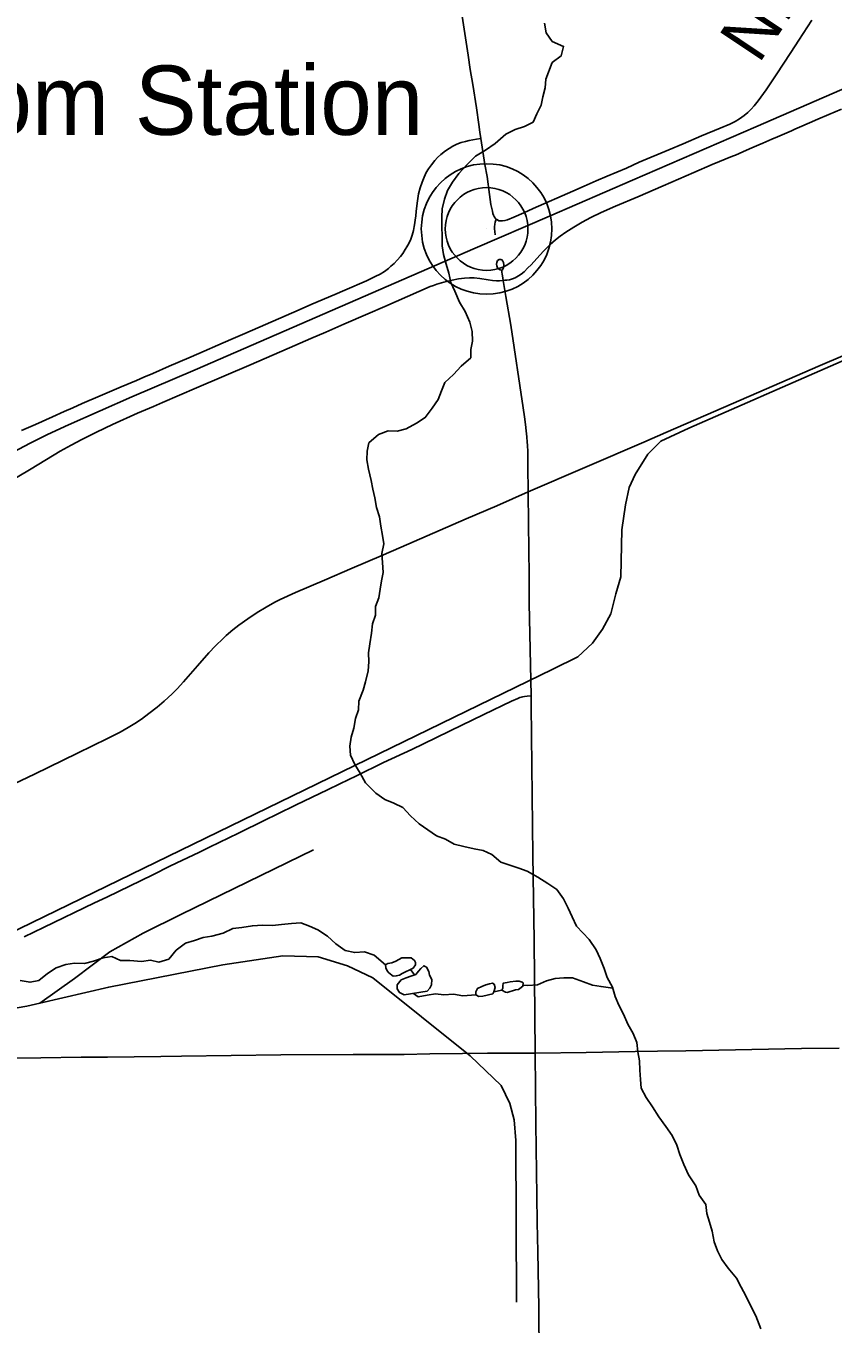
# Model space of a CAD drawing. Extents: x 0 to 34, y 0 to 22.
# Drawn here: x 14.293 to 16.593, y 8.341 to 12.039 of the extents above; entities that cross this region are included whole.
import ezdxf

# ---------------------------------------------------------------- set-up
doc = ezdxf.new("R2010")
doc.units = 0
for name, color, linetype in [('GM_X_County_Road', 7, 'Continuous'), ('GM_X_County_Road_Text', 7, 'Continuous'), ('GM_X_Minor_Lake', 7, 'Continuous'), ('GM_X_Minor_River', 7, 'Continuous'), ('GM_X_Rail_Line', 7, 'Continuous'), ('GM_X_Township_Road', 7, 'Continuous'), ('GM_X_Unincorporated', 7, 'Continuous'), ('GM_X_Unincorporated_Location', 7, 'Continuous'), ('GM_X_Unincorporated_Text', 7, 'Continuous')]:
    doc.layers.add(name, color=color, linetype=linetype)

msp = doc.modelspace()

# ---------------------------------------------------------------- linework, layer by layer
at = {"layer": 'GM_X_County_Road'}
for points in [[(15.5893, 11.7179), (15.5867, 11.7367), (15.5837, 11.7582), (15.5764, 11.8058), (15.5661, 11.8717), (15.5592, 11.9146), (15.5526, 11.956), (15.5417, 12.0297), (15.5308, 12.0972)], [(15.6332, 11.4882), (15.6368, 11.4861), (15.6409, 11.4841), (15.6458, 11.4832), (15.6512, 11.4833), (15.6578, 11.4843), (15.6648, 11.4865), (15.6833, 11.4942), (15.7118, 11.5064), (15.7387, 11.5184), (15.8512, 11.5678), (15.8839, 11.5822), (15.918, 11.5973), (15.9493, 11.6112), (16.0038, 11.6338), (16.0406, 11.6504), (16.1251, 11.6862), (16.1653, 11.7028), (16.2181, 11.7256), (16.2712, 11.7476), (16.2982, 11.7593), (16.3134, 11.7669), (16.3266, 11.7747), (16.3392, 11.7835), (16.3497, 11.7923), (16.3596, 11.802), (16.3678, 11.8112), (16.3791, 11.8258), (16.4017, 11.8573), (16.4304, 11.8998), (16.4725, 11.9632), (16.4953, 11.9985), (16.5327, 12.0557)], [(15.6332, 11.4882), (15.6301, 11.4912), (15.627, 11.4956), (15.6252, 11.4995), (15.6236, 11.5046), (15.6222, 11.5108), (15.6181, 11.5305), (15.6142, 11.5585), (15.6068, 11.6102), (15.6007, 11.6446), (15.5893, 11.7179)], [(15.6303, 11.4436), (15.6288, 11.4534), (15.6283, 11.4611), (15.6285, 11.4665), (15.629, 11.4742), (15.6301, 11.4794), (15.6332, 11.4882)]]:
    msp.add_lwpolyline(points, dxfattribs=at)
at = {"layer": 'GM_X_Minor_Lake'}
for p, q in [((15.3651, 9.339), (15.3961, 9.3546)), ((15.3705, 9.2783), (15.4367, 9.2886)), ((15.6639, 9.2855), (15.6875, 9.2924)), ((15.5949, 9.2752), (15.6233, 9.2813))]:
    msp.add_line(p, q, dxfattribs=at)
for points in [[(15.3961, 9.3546), (15.4027, 9.3641), (15.4026, 9.3708), (15.4006, 9.3764), (15.3911, 9.3839), (15.3788, 9.3838), (15.3636, 9.3836), (15.3467, 9.3749), (15.3354, 9.37), (15.324, 9.3679), (15.3174, 9.3641), (15.3185, 9.3555), (15.3224, 9.347), (15.3272, 9.3414), (15.3396, 9.3321), (15.3481, 9.3322), (15.3576, 9.3342), (15.3651, 9.339)], [(15.4367, 9.2886), (15.4441, 9.2972), (15.4488, 9.3068), (15.4495, 9.322), (15.4428, 9.3342), (15.4408, 9.3446), (15.434, 9.3569), (15.4264, 9.3615), (15.4179, 9.3539), (15.4114, 9.3462), (15.4039, 9.3366), (15.3898, 9.3317), (15.3766, 9.3268), (15.3624, 9.3209), (15.3503, 9.3066), (15.3504, 9.2961), (15.3572, 9.2848), (15.3705, 9.2783)], [(15.6233, 9.2813), (15.626, 9.287), (15.6297, 9.2994), (15.6267, 9.3088), (15.622, 9.3116), (15.6135, 9.3096), (15.6031, 9.3067), (15.5918, 9.3027), (15.5795, 9.2969), (15.5749, 9.2873), (15.575, 9.2788), (15.5836, 9.2742), (15.5949, 9.2752)], [(15.6875, 9.2924), (15.696, 9.2935), (15.6998, 9.2964), (15.7092, 9.3031), (15.71, 9.3126), (15.7072, 9.3145), (15.6986, 9.3173), (15.6939, 9.3172), (15.6891, 9.3171), (15.6731, 9.316), (15.6646, 9.314), (15.6532, 9.312), (15.6514, 9.3044), (15.6515, 9.2977), (15.6487, 9.292), (15.6592, 9.2864), (15.6639, 9.2855)]]:
    msp.add_lwpolyline(points, dxfattribs=at)
at = {"layer": 'GM_X_Minor_River'}
for points in [[(15.6302, 11.7038), (15.6602, 11.7307), (15.6866, 11.7434), (15.7139, 11.7522), (15.7384, 11.7648), (15.7486, 11.7887), (15.7615, 11.8135), (15.766, 11.8373), (15.7724, 11.8621), (15.774, 11.8868), (15.7924, 11.9345), (15.8177, 11.9537), (15.825, 11.9804), (15.7927, 11.9943), (15.7753, 12.0197), (15.7703, 12.0472)], [(15.9289, 9.3816), (15.9182, 9.4071), (15.898, 9.4363), (15.8616, 9.4739), (15.849, 9.5003), (15.8383, 9.5258), (15.8247, 9.5522), (15.8055, 9.5786), (15.7797, 9.5953), (15.7511, 9.614), (15.7216, 9.6307), (15.6978, 9.639), (15.6721, 9.6482), (15.6465, 9.6564), (15.6207, 9.678), (15.5959, 9.69), (15.5703, 9.6945), (15.5409, 9.7008), (15.5133, 9.708), (15.4886, 9.722), (15.4629, 9.7312), (15.4381, 9.7489), (15.4133, 9.7657), (15.3884, 9.7882), (15.3673, 9.8127), (15.3416, 9.8247), (15.3159, 9.8348), (15.2902, 9.8535), (15.2605, 9.8826), (15.245, 9.9099), (15.2305, 9.9345), (15.2179, 9.9609), (15.2157, 9.9874), (15.2193, 10.0122), (15.2275, 10.0379), (15.2319, 10.0655), (15.2402, 10.0902), (15.2418, 10.1149), (15.2537, 10.1464), (15.2601, 10.1702), (15.2683, 10.2016), (15.2699, 10.2273), (15.2686, 10.2529), (15.2731, 10.2786), (15.2775, 10.309), (15.28, 10.3356), (15.2892, 10.3604), (15.2889, 10.3851), (15.2981, 10.4098), (15.3026, 10.4346), (15.3061, 10.4583), (15.3106, 10.4821), (15.3093, 10.5106), (15.3071, 10.5362), (15.3125, 10.5638), (15.3094, 10.5875), (15.3043, 10.614), (15.3003, 10.6405), (15.2914, 10.667), (15.2873, 10.6945), (15.2814, 10.7191), (15.2764, 10.7437), (15.2694, 10.7759), (15.2644, 10.8024), (15.265, 10.8271), (15.2704, 10.8509), (15.2976, 10.875), (15.325, 10.8857), (15.3506, 10.8841), (15.376, 10.8911), (15.4062, 10.9076), (15.4306, 10.923), (15.4502, 10.9498), (15.4679, 10.9747), (15.4771, 10.9995), (15.4863, 11.0234), (15.5116, 11.0455), (15.5331, 11.0695), (15.5603, 11.0935), (15.561, 11.1173), (15.5655, 11.141), (15.5642, 11.1685), (15.5582, 11.1951), (15.5446, 11.2253), (15.5282, 11.2517), (15.5146, 11.2828), (15.5039, 11.3083), (15.498, 11.3349), (15.4901, 11.3604), (15.4832, 11.3878), (15.4791, 11.4125), (15.4782, 11.4941), (15.4789, 11.5179), (15.4852, 11.5455), (15.4944, 11.5702), (15.5083, 11.5941), (15.526, 11.6181), (15.5504, 11.644), (15.5738, 11.668), (15.602, 11.6854), (15.6302, 11.7038)], [(15.3174, 9.3641), (15.285, 9.3912), (15.2574, 9.4013), (15.2299, 9.3991), (15.2024, 9.4045), (15.1757, 9.4241), (15.1518, 9.4457), (15.1251, 9.4634), (15.1013, 9.4745), (15.0766, 9.4837), (15.0501, 9.4815), (15.0207, 9.4793), (14.9952, 9.4761), (14.9668, 9.4767), (14.9384, 9.4755), (14.9082, 9.4704), (14.8826, 9.4672), (14.8553, 9.4546), (14.8223, 9.4456), (14.7977, 9.4416), (14.7732, 9.4337), (14.7477, 9.4258), (14.7214, 9.4055), (14.6999, 9.3806), (14.6716, 9.3718), (14.6479, 9.3772), (14.6224, 9.3731), (14.5892, 9.3765), (14.5627, 9.3762), (14.538, 9.3873), (14.5134, 9.3841), (14.4851, 9.3743), (14.4596, 9.3674), (14.4312, 9.3689), (14.4066, 9.3649), (14.3792, 9.3551), (14.3548, 9.3396), (14.3295, 9.3194), (14.3049, 9.3143), (14.2764, 9.3197)], [(16.3868, 8.3268), (16.3731, 8.3637), (16.3596, 8.3901), (16.3441, 8.4212), (16.3305, 8.4458), (16.3179, 8.4712), (16.2939, 8.4994), (16.2757, 8.5248), (16.2631, 8.5494), (16.2543, 8.5749), (16.2482, 8.6052), (16.2404, 8.6307), (16.2335, 8.6553), (16.2303, 8.6809), (16.2111, 8.7082), (16.2013, 8.7347), (16.1811, 8.7657), (16.1675, 8.795), (16.1558, 8.8233), (16.148, 8.8498), (16.1344, 8.8781), (16.1161, 8.9036), (16.0959, 8.9308), (16.0785, 8.9591), (16.0602, 8.9864), (16.0457, 9.0128), (16.0445, 9.0375), (16.0423, 9.064), (16.0411, 9.0906), (16.0361, 9.1162), (16.0339, 9.1427), (16.0232, 9.1682), (16.0077, 9.1946), (15.996, 9.223), (15.9825, 9.2494), (15.9718, 9.2739), (15.9639, 9.3004), (15.9494, 9.3278), (15.9406, 9.3533), (15.9289, 9.3816)], [(15.4004, 9.3354), (15.3885, 9.3507)], [(15.9648, 9.2974), (15.9317, 9.3019), (15.907, 9.3064), (15.8814, 9.3156), (15.85, 9.3266), (15.8254, 9.3273), (15.8008, 9.3251), (15.7762, 9.3182), (15.7508, 9.3074), (15.7234, 9.3052), (15.7094, 9.306)], [(15.575, 9.2788), (15.5381, 9.2755), (15.5116, 9.28), (15.4841, 9.2787), (15.4604, 9.2813), (15.4358, 9.2772), (15.4103, 9.2731), (15.3975, 9.2825)], [(15.6487, 9.292), (15.6261, 9.2872)]]:
    msp.add_lwpolyline(points, dxfattribs=at)
at = {"layer": 'GM_X_Rail_Line'}
for points in [[(18.6712, 11.9797), (17.7965, 11.5996), (16.1817, 10.893), (16.1016, 10.8556), (16.0651, 10.819), (16.0291, 10.7614), (16.0117, 10.7238), (16.0013, 10.6748), (15.9912, 10.6032), (15.988, 10.4696), (15.9742, 10.4211), (15.9592, 10.364), (15.9356, 10.3204), (15.9074, 10.2808), (15.8654, 10.2415), (15.7943, 10.2063), (14.1322, 9.3985), (13.8231, 9.242), (13.7678, 9.2202), (13.679, 9.1945)], [(14.2563, 10.8249), (14.3049, 10.8506), (14.3545, 10.8748), (14.4143, 10.9027), (14.595, 10.9819), (14.775, 11.0593), (15.0072, 11.1599), (15.5727, 11.4055), (15.7849, 11.4972), (16.0211, 11.5991), (16.3726, 11.7519), (16.8851, 11.9739)], [(14.3323, 9.2546), (14.4312, 9.325), (14.5322, 9.4011), (14.6274, 9.4541), (14.7359, 9.5079), (15.1124, 9.6913)], [(14.3323, 9.2546), (14.5287, 9.3006), (14.8537, 9.3637), (15.0248, 9.39), (15.1252, 9.3865), (15.2093, 9.3613), (15.2816, 9.3272), (15.5584, 9.1048), (15.6474, 9.0205), (15.6721, 8.9691), (15.6841, 8.9223), (15.689, 8.8631), (15.6906, 8.4032)], [(13.679, 9.1945), (13.8272, 9.187), (14.0474, 9.2037), (14.2951, 9.2459), (14.3323, 9.2546)]]:
    msp.add_lwpolyline(points, dxfattribs=at)
at = {"layer": 'GM_X_Township_Road'}
for points in [[(16.1163, 10.8804), (16.2304, 10.9297), (16.4029, 11.0046), (16.5498, 11.0682), (16.7054, 11.1353), (16.8238, 11.1864), (16.9594, 11.2449), (17.0179, 11.2701), (17.1618, 11.3327), (17.2616, 11.376), (17.4399, 11.4533), (17.5883, 11.5174), (17.7723, 11.597), (17.8978, 11.6513), (18.0734, 11.727), (18.3016, 11.8257), (18.4757, 11.9009), (18.5727, 11.9429), (18.6712, 11.9855)], [(14.3906, 10.827), (14.4218, 10.8445), (14.452, 10.8604), (14.4937, 10.8812), (14.54, 10.9033), (14.6108, 10.9353), (14.6564, 10.9551), (14.6822, 10.9659), (14.7792, 11.0077), (14.9347, 11.0747), (15.0588, 11.1283), (15.1045, 11.148), (15.1472, 11.1666), (15.1984, 11.1891), (15.2668, 11.2189), (15.3152, 11.24), (15.445, 11.2961), (15.4538, 11.2996), (15.464, 11.3028), (15.4833, 11.3087), (15.5075, 11.3147), (15.5257, 11.3183), (15.5427, 11.3205), (15.5566, 11.3214), (15.5706, 11.3209), (15.586, 11.3189), (15.6104, 11.3153), (15.6227, 11.3136), (15.6335, 11.3127), (15.6419, 11.3127), (15.6529, 11.3138), (15.6575, 11.3142), (15.6628, 11.3149), (15.6704, 11.316), (15.6794, 11.3186), (15.6865, 11.3216), (15.6961, 11.3266), (15.7039, 11.3318), (15.7123, 11.3386), (15.7235, 11.3494), (15.7321, 11.3584), (15.7572, 11.3859), (15.769, 11.3983), (15.7866, 11.4158), (15.8017, 11.4293), (15.815, 11.4399), (15.8315, 11.4516), (15.8537, 11.4659), (15.8779, 11.48), (15.9026, 11.4931), (15.9321, 11.5071), (15.9733, 11.5254), (16.0361, 11.5523), (16.1089, 11.5838), (16.196, 11.6211), (16.2487, 11.6438), (16.306, 11.6675), (16.3145, 11.6711), (16.3459, 11.6846), (16.3616, 11.6914), (16.3816, 11.6999), (16.393, 11.7048), (16.4186, 11.7159), (16.4343, 11.7227), (16.4613, 11.7345), (16.4741, 11.7402), (16.4841, 11.7445), (16.4969, 11.7501), (16.5253, 11.7625), (16.5496, 11.773), (16.5809, 11.7866), (16.6165, 11.8021)], [(14.28, 10.8865), (14.32, 10.9034), (14.3683, 10.9248), (14.4022, 10.9401), (14.4263, 10.951), (14.4533, 10.9629), (14.5045, 10.9854), (14.5644, 11.0109), (14.6076, 11.0285), (14.6289, 11.0378), (14.6545, 11.0488), (14.7015, 11.0693), (14.757, 11.0937), (14.7855, 11.1059), (14.8554, 11.1362), (14.8839, 11.1485), (14.9167, 11.1627), (15.0349, 11.2143), (15.0719, 11.2303), (15.1075, 11.246), (15.1732, 11.2741), (15.2017, 11.2864), (15.2629, 11.3129), (15.2882, 11.3248), (15.3019, 11.3319), (15.315, 11.3397), (15.3258, 11.3477), (15.3329, 11.3542), (15.3421, 11.3622), (15.3508, 11.3716), (15.3598, 11.382), (15.3668, 11.391), (15.374, 11.4015), (15.3787, 11.4093), (15.3836, 11.4191), (15.3894, 11.4316), (15.3938, 11.443), (15.3974, 11.4563), (15.3994, 11.4672), (15.4011, 11.4782), (15.4022, 11.4867), (15.4038, 11.4974), (15.4052, 11.5112), (15.4089, 11.5406), (15.412, 11.5607), (15.4162, 11.5774), (15.4216, 11.5938), (15.4275, 11.6084), (15.4338, 11.6211), (15.4402, 11.6319), (15.4482, 11.6436), (15.458, 11.6558), (15.4655, 11.6639), (15.4747, 11.6725), (15.4885, 11.683), (15.4989, 11.6901), (15.5098, 11.6964), (15.5211, 11.7019), (15.5329, 11.7065), (15.545, 11.71), (15.5558, 11.7124), (15.5666, 11.7142), (15.5772, 11.7159), (15.5893, 11.7179)], [(15.7202, 10.866), (15.7201, 10.8682), (15.7182, 10.8853), (15.7161, 10.9031), (15.7132, 10.9256), (15.7095, 10.9506), (15.6742, 11.1866), (15.6605, 11.2679), (15.6529, 11.3138), (15.6506, 11.3273), (15.6498, 11.3321), (15.649, 11.3378), (15.6488, 11.3403), (15.6493, 11.343), (15.6506, 11.3445), (15.652, 11.3463), (15.6537, 11.3494), (15.6547, 11.3536), (15.6545, 11.3587), (15.6535, 11.3649), (15.652, 11.3692), (15.649, 11.3726), (15.6462, 11.3737), (15.6418, 11.3737), (15.637, 11.3704), (15.6345, 11.3648), (15.6342, 11.36), (15.635, 11.3554), (15.6369, 11.3495), (15.6407, 11.3461), (15.6446, 11.344), (15.6482, 11.3429)], [(15.7244, 10.7117), (16.0534, 10.8533), (16.1163, 10.8804)], [(15.7581, 8.1139), (15.7548, 8.3455), (15.7544, 8.3875), (15.7518, 8.546), (15.7498, 8.6299), (15.7488, 8.7061), (15.7458, 8.9113), (15.744, 9.1126), (15.7412, 9.4344), (15.7373, 9.6751), (15.7327, 10.1025), (15.7322, 10.1303), (15.7273, 10.3942), (15.7264, 10.4719), (15.7255, 10.5481), (15.7246, 10.6208), (15.7244, 10.7117), (15.7235, 10.7835), (15.7233, 10.8052), (15.723, 10.8173), (15.7227, 10.8275), (15.7217, 10.8423), (15.7211, 10.8553), (15.7202, 10.866)], [(14.228, 10.7299), (14.3081, 10.7775), (14.3906, 10.827)], [(14.2415, 9.871), (14.317, 9.9076), (14.4401, 9.9671), (14.5253, 10.0086), (14.5614, 10.0269), (14.5844, 10.0397), (14.6029, 10.0511), (14.6222, 10.0641), (14.6434, 10.0798), (14.6666, 10.098), (14.6866, 10.1152), (14.7095, 10.1363), (14.7238, 10.1505), (14.7419, 10.1698), (14.7815, 10.2156), (14.8144, 10.2529), (14.8335, 10.2733), (14.8546, 10.2939), (14.8637, 10.3023), (14.8826, 10.3185), (14.8997, 10.3319), (14.9249, 10.3501), (14.9521, 10.368), (14.9773, 10.3833), (15.0018, 10.3969), (15.017, 10.4046), (15.0609, 10.4243), (15.1437, 10.4599), (15.2221, 10.4938), (15.3049, 10.5295), (15.362, 10.554), (15.4361, 10.586), (15.5472, 10.6344), (15.6343, 10.6719), (15.7244, 10.7117)], [(14.2881, 9.4436), (14.3427, 9.47), (14.488, 9.5405), (14.5231, 9.5572), (14.6547, 9.6208), (14.7032, 9.6447), (14.7394, 9.662), (14.7854, 9.6843), (14.8161, 9.6993), (14.8986, 9.7391), (14.9736, 9.7758), (15.0084, 9.7928), (15.0628, 9.8194), (15.1522, 9.8623), (15.1871, 9.8792), (15.2344, 9.9022), (15.3122, 9.9403), (15.3923, 9.9779), (15.4608, 10.0111), (15.5015, 10.0305), (15.5978, 10.077), (15.6761, 10.1149), (15.6945, 10.1232), (15.7002, 10.1254), (15.7046, 10.1267), (15.7087, 10.1278), (15.714, 10.1288), (15.7207, 10.1297), (15.7322, 10.1303)], [(14.2672, 9.0979), (14.3356, 9.099), (14.4506, 9.1005), (14.5253, 9.1014), (14.6776, 9.1029), (14.7363, 9.1036), (15.0189, 9.1072), (15.225, 9.1081), (15.3704, 9.109), (15.4435, 9.1107), (15.5367, 9.1116), (15.6082, 9.112), (15.744, 9.1126), (15.8891, 9.1144), (16.029, 9.1174), (16.0927, 9.118), (16.1735, 9.1188), (16.5029, 9.1255), (16.6101, 9.1269)]]:
    msp.add_lwpolyline(points, dxfattribs=at)
at = {"layer": 'GM_X_Unincorporated'}
for radius in [0.186, 0.1179]:
    msp.add_circle((15.6056, 11.4605), radius, dxfattribs=at)
at = {"layer": 'GM_X_Unincorporated_Location'}
msp.add_line((15.6056, 11.4605), (15.6056, 11.4605), dxfattribs=at)

# ---------------------------------------------------------------- texts
at = {"layer": 'GM_X_County_Road_Text'}
msp.add_text('NICHOLS', height=0.14205, rotation=56.3099, dxfattribs=at).set_placement((16.3811, 11.9285))
at = {"layer": 'GM_X_Unincorporated_Text'}
msp.add_text('Freedom Station', height=0.197443, rotation=0, dxfattribs=at).set_placement((13.4734, 11.7286))

doc.saveas('drawing.dxf')
